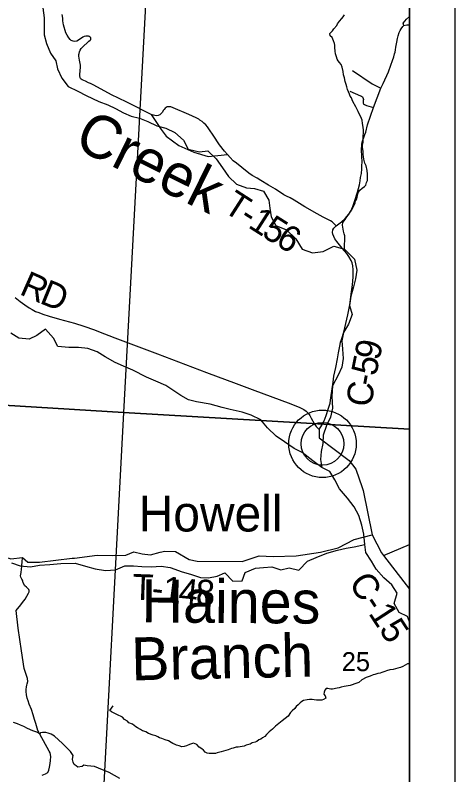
# Model space of a CAD drawing. Extents: x 0 to 45.4, y -2.2 to 22.
# Drawn here: x 8.031 to 9, y 16.232 to 17.906 of the extents above; entities that cross this region are included whole.
import ezdxf

# ---------------------------------------------------------------- set-up
doc = ezdxf.new("R2010")
doc.units = 0
for name, color, linetype in [('GM_X_Corporation', 7, 'Continuous'), ('GM_X_County_Road', 7, 'Continuous'), ('GM_X_County_Road_Text', 7, 'Continuous'), ('GM_X_Minor_River', 7, 'Continuous'), ('GM_X_Minor_River_Text', 7, 'Continuous'), ('GM_X_Section_Text', 7, 'Continuous'), ('GM_X_Township_Road', 7, 'Continuous'), ('GM_X_Township_Road_Text', 7, 'Continuous'), ('GM_X_Unincorporated', 7, 'Continuous'), ('GM_X_Unincorporated_Location', 7, 'Continuous'), ('GM_X_Unincorporated_Text', 7, 'Continuous'), ('SH_Data', 7, 'Continuous')]:
    doc.layers.add(name, color=color, linetype=linetype)

msp = doc.modelspace()

# ---------------------------------------------------------------- linework, layer by layer
at = {"layer": 'GM_X_Corporation'}
for points in [[(5.6021, 14.1), (7.0413, 14.1), (7.1146, 14.1136), (7.5608, 14.2194), (7.6244, 14.2444), (8.0832, 14.3972), (8.4711, 14.5406), (8.5907, 14.5823), (8.8228, 14.6772), (8.9, 14.7192), (8.9, 20.9), (2.1, 20.9)], [(5.6021, 14.1), (7.0413, 14.1), (7.1146, 14.1136), (7.5608, 14.2194), (7.6244, 14.2444), (8.0832, 14.3972), (8.4711, 14.5406), (8.5907, 14.5823), (8.8228, 14.6772), (8.9, 14.7192), (8.9, 20.9), (6.2942, 20.9), (6.2882, 20.8226), (6.2789, 20.7002), (6.2588, 20.2929), (6.2538, 20.2076), (6.2346, 20.0088), (6.2236, 19.8542), (6.181, 19.2539), (6.1763, 19.1885), (6.1061, 18.1607), (5.642, 18.1908)]]:
    msp.add_lwpolyline(points, dxfattribs=at)
for points in [[(7.2262, 18.1039), (8.3245, 18.0384), (8.2701, 17.0306), (7.1661, 17.098)], [(8.9, 16.9941), (8.9, 18.0073), (8.3245, 18.0384), (8.2701, 17.0306)], [(8.2701, 17.0306), (8.2164, 16.0186), (7.1036, 16.0876), (7.1661, 17.098)], [(8.9, 15.9811), (8.9, 16.9941), (8.2701, 17.0306), (8.2164, 16.0186)]]:
    msp.add_lwpolyline(points, close=True, dxfattribs=at)
at = {"layer": 'GM_X_County_Road'}
for points in [[(8.8819, 17.8762), (8.8854, 17.8817), (8.8874, 17.8837), (8.8941, 17.8853), (8.8994, 17.8849), (8.9, 17.8847)], [(8.7009, 16.9934), (8.7068, 17.0031), (8.7118, 17.012), (8.7163, 17.0242), (8.7211, 17.0379), (8.7251, 17.0515), (8.7261, 17.0576), (8.7277, 17.0683), (8.7318, 17.0973), (8.7336, 17.1111), (8.7376, 17.1297), (8.7411, 17.1487), (8.7436, 17.1619), (8.7457, 17.1732), (8.7472, 17.1806), (8.7484, 17.186), (8.7502, 17.1918), (8.7552, 17.2079), (8.7645, 17.2457), (8.7685, 17.2683), (8.7724, 17.2968), (8.7744, 17.3124), (8.7758, 17.3289), (8.776, 17.345), (8.7751, 17.3542), (8.7741, 17.3604), (8.7715, 17.3659), (8.7664, 17.3742), (8.7619, 17.381), (8.752, 17.3929), (8.7402, 17.4073), (8.7359, 17.4134), (8.7334, 17.4184), (8.7313, 17.4235), (8.7302, 17.4272), (8.7313, 17.433), (8.7331, 17.437), (8.7386, 17.4424), (8.7503, 17.451), (8.7586, 17.4583), (8.7666, 17.4681), (8.7713, 17.4751), (8.7732, 17.4799), (8.7752, 17.4848), (8.78, 17.498), (8.7858, 17.5163), (8.7896, 17.5324), (8.7913, 17.5409), (8.7925, 17.5484), (8.794, 17.5575), (8.7949, 17.5677), (8.7951, 17.5731), (8.7955, 17.5843), (8.7952, 17.5936), (8.7947, 17.611), (8.7949, 17.6189), (8.7951, 17.622), (8.7961, 17.6263), (8.7973, 17.631), (8.7996, 17.6369), (8.8018, 17.6433), (8.8039, 17.6488), (8.8076, 17.6649), (8.8208, 17.7029), (8.8371, 17.7454), (8.8419, 17.7558), (8.8535, 17.7816), (8.8592, 17.796), (8.863, 17.8067), (8.8656, 17.8145), (8.8674, 17.8212), (8.8683, 17.8248), (8.8692, 17.83), (8.8703, 17.8357), (8.8722, 17.8471), (8.8736, 17.8547), (8.8754, 17.8611), (8.8777, 17.8682), (8.8794, 17.8723), (8.8819, 17.8762)], [(8.0309, 17.2842), (8.0421, 17.2756), (8.0522, 17.2682), (8.0616, 17.2616), (8.0685, 17.2577), (8.076, 17.2535), (8.083, 17.2507), (8.092, 17.2477), (8.1063, 17.2433), (8.129, 17.2366), (8.1615, 17.2272), (8.1823, 17.2211), (8.2057, 17.2128), (8.2147, 17.2093), (8.2507, 17.1955), (8.3446, 17.16), (8.4525, 17.1191), (8.5181, 17.0946), (8.5595, 17.0791), (8.6325, 17.0518), (8.6568, 17.0426), (8.6675, 17.0376), (8.6726, 17.0333), (8.6765, 17.0295), (8.6802, 17.0243), (8.6831, 17.0183), (8.69, 17.0063), (8.6942, 17), (8.7009, 16.9934), (8.7012, 16.9748), (8.7674, 16.9251), (8.7816, 16.9061), (8.7959, 16.8653), (8.7982, 16.8588), (8.8176, 16.7613)], [(8.8176, 16.7613), (8.8384, 16.7214), (8.8425, 16.7152), (8.9, 16.6414)]]:
    msp.add_lwpolyline(points, dxfattribs=at)
at = {"layer": 'GM_X_Minor_River'}
for points in [[(8.0896, 17.9392), (8.0948, 17.9004), (8.0946, 17.8632), (8.0998, 17.8442), (8.1088, 17.8229), (8.1209, 17.8054), (8.1246, 17.7879), (8.1336, 17.7674), (8.1479, 17.7491), (8.1691, 17.7392), (8.1872, 17.7292), (8.2152, 17.7162), (8.2349, 17.7085), (8.2522, 17.7009), (8.2696, 17.691), (8.287, 17.6841), (8.3052, 17.6794), (8.3233, 17.6718), (8.343, 17.6626), (8.3634, 17.6572), (8.383, 17.648), (8.4019, 17.6312), (8.4124, 17.6107), (8.4374, 17.6053), (8.4556, 17.6075), (8.4737, 17.59), (8.488, 17.5702), (8.5015, 17.5511), (8.5189, 17.5336), (8.5408, 17.5259), (8.5582, 17.5243), (8.5787, 17.5182), (8.5899, 17.4984), (8.5921, 17.4809), (8.5951, 17.4619), (8.6056, 17.4429), (8.629, 17.4329), (8.6494, 17.4131), (8.6637, 17.391), (8.6864, 17.3826), (8.7099, 17.3855), (8.7334, 17.3976), (8.7569, 17.3907), (8.7787, 17.3685), (8.7839, 17.3442), (8.7808, 17.3252), (8.777, 17.3078), (8.7708, 17.2873), (8.7677, 17.2668), (8.7737, 17.247), (8.766, 17.225), (8.7546, 17.2068), (8.7507, 17.1885), (8.7522, 17.1703), (8.7536, 17.1498), (8.7513, 17.1308), (8.7429, 17.1133), (8.7306, 17.0898), (8.729, 17.0662), (8.7305, 17.0404), (8.7258, 17.0206), (8.7174, 17.0017), (8.7098, 16.9804), (8.7089, 16.9622), (8.7058, 16.9447), (8.7042, 16.9272), (8.7072, 16.9097)], [(8.7569, 17.3907), (8.7574, 17.4199), (8.7559, 17.4245), (8.7545, 17.4302), (8.7535, 17.4394), (8.7528, 17.4432), (8.7533, 17.4493), (8.7587, 17.4564), (8.7622, 17.4617), (8.7654, 17.4665), (8.7704, 17.4737), (8.7735, 17.4789), (8.7759, 17.4835), (8.7775, 17.4869), (8.7802, 17.4921), (8.7806, 17.4955), (8.7834, 17.5001), (8.7846, 17.505), (8.7854, 17.5091), (8.7862, 17.5125), (8.7874, 17.5163), (8.7909, 17.5208), (8.7959, 17.5253), (8.8009, 17.5286), (8.804, 17.532), (8.8056, 17.5373), (8.8076, 17.5418), (8.8078, 17.5513), (8.8075, 17.5563), (8.8065, 17.5639), (8.8048, 17.5742), (8.8014, 17.5799), (8.7997, 17.5891), (8.799, 17.594), (8.798, 17.5997), (8.7977, 17.6062), (8.7964, 17.6157), (8.7965, 17.6199), (8.7977, 17.6267), (8.7982, 17.6332), (8.7986, 17.654), (8.7983, 17.659), (8.7972, 17.6636), (8.7969, 17.6677), (8.7955, 17.675), (8.7926, 17.6826), (8.7882, 17.6907), (8.7868, 17.6941), (8.7839, 17.6999), (8.782, 17.7045), (8.7754, 17.7164), (8.774, 17.7198), (8.7722, 17.7244), (8.7696, 17.7279), (8.7678, 17.7321), (8.7656, 17.7374), (8.7638, 17.7424), (8.762, 17.7481), (8.7606, 17.7535), (8.7584, 17.7603), (8.7566, 17.768), (8.7549, 17.7752), (8.7539, 17.7824), (8.7514, 17.792), (8.7496, 17.7973), (8.7459, 17.8019), (8.7429, 17.8058), (8.7407, 17.8096), (8.7389, 17.8142), (8.7367, 17.8211), (8.7361, 17.8268), (8.7359, 17.8352), (8.7356, 17.8401), (8.7349, 17.8443), (8.7327, 17.85), (8.7294, 17.8569), (8.725, 17.8612), (8.7247, 17.8657), (8.7304, 17.8721), (8.7336, 17.8766), (8.7397, 17.8837), (8.7413, 17.8871), (8.746, 17.8931), (8.751, 17.8991), (8.7537, 17.9028), (8.7572, 17.9073)], [(8.9, 16.5695), (8.896, 16.5811), (8.8771, 16.5896), (8.8666, 16.6094), (8.8727, 16.6322), (8.8614, 16.6505), (8.8433, 16.6665), (8.8267, 16.6856), (8.8162, 16.7032), (8.8042, 16.7222), (8.802, 16.7397), (8.7998, 16.7626), (8.7953, 16.7824), (8.7886, 16.8037), (8.7781, 16.8227), (8.7637, 16.8418), (8.7456, 16.8624), (8.7359, 16.8822), (8.7246, 16.9005), (8.7072, 16.9097), (8.6868, 16.9242), (8.6634, 16.9426), (8.646, 16.951), (8.6249, 16.9663), (8.606, 16.9785), (8.5871, 16.9968), (8.5728, 17.0144), (8.5509, 17.0251), (8.5312, 17.0312), (8.5047, 17.0374), (8.4873, 17.042), (8.4609, 17.049), (8.4306, 17.0544), (8.4132, 17.0583), (8.3958, 17.0682), (8.3633, 17.0904), (8.3414, 17.0996), (8.3202, 17.1088), (8.29, 17.1241), (8.2696, 17.1325), (8.2515, 17.1409), (8.2295, 17.1532), (8.2114, 17.1647), (8.191, 17.1716), (8.1706, 17.1739), (8.1493, 17.174), (8.1251, 17.1764), (8.1153, 17.1946), (8.098, 17.2145), (8.079, 17.2001), (8.0616, 17.1926), (8.0389, 17.1942), (8.0215, 17.2056)], [(8.0232, 16.6992), (8.0422, 16.693), (8.0649, 16.6907), (8.0846, 16.6944), (8.1073, 16.6959), (8.1315, 16.6981), (8.1634, 16.6987), (8.186, 16.6918), (8.2072, 16.6864), (8.2299, 16.6825), (8.2519, 16.6839), (8.2731, 16.693), (8.2921, 16.6929), (8.3103, 16.6913), (8.3307, 16.6905), (8.3527, 16.6919), (8.3723, 16.6888), (8.3988, 16.6796), (8.4177, 16.6742), (8.4397, 16.6673), (8.4571, 16.6664), (8.476, 16.6702), (8.4935, 16.677), (8.5108, 16.6586), (8.5313, 16.6593), (8.5382, 16.6783), (8.5609, 16.6874), (8.5783, 16.6888), (8.5965, 16.6903), (8.6162, 16.6841), (8.6351, 16.6886), (8.6563, 16.6832), (8.6753, 16.7029), (8.6943, 16.7112), (8.7178, 16.7203), (8.7413, 16.727), (8.7603, 16.7315), (8.7785, 16.7345), (8.802, 16.7397), (8.8004, 16.739)], [(8.9, 16.4768), (8.8955, 16.4766), (8.8852, 16.4707), (8.8806, 16.4689), (8.8745, 16.4674), (8.8695, 16.466), (8.8638, 16.4646), (8.857, 16.4632), (8.8498, 16.461), (8.8456, 16.4599), (8.8395, 16.4578), (8.8357, 16.4563), (8.83, 16.4553), (8.8239, 16.4535), (8.8201, 16.4524), (8.8132, 16.4498), (8.8048, 16.4466), (8.7949, 16.4418), (8.7883, 16.4354), (8.78, 16.4325), (8.7739, 16.4307), (8.7697, 16.4293), (8.7602, 16.4275), (8.756, 16.4265), (8.7495, 16.425), (8.7453, 16.424), (8.7404, 16.4229), (8.7305, 16.4212), (8.7267, 16.4212), (8.7233, 16.4217), (8.7199, 16.4225), (8.7165, 16.4226), (8.7134, 16.4184), (8.7122, 16.4143), (8.7114, 16.4101), (8.714, 16.4059), (8.7154, 16.4009), (8.7108, 16.3979), (8.7066, 16.3968), (8.7024, 16.3965), (8.6952, 16.3967), (8.69, 16.3975), (8.6858, 16.398), (8.6797, 16.3981), (8.6748, 16.3974), (8.6664, 16.3956), (8.6626, 16.3934), (8.6592, 16.3904), (8.6549, 16.3863), (8.6507, 16.383), (8.6476, 16.3781), (8.6414, 16.3732), (8.638, 16.3691), (8.6329, 16.3616), (8.6198, 16.3511), (8.6118, 16.3452), (8.6049, 16.3392), (8.5983, 16.3328), (8.591, 16.3265), (8.5849, 16.3209), (8.5814, 16.3168), (8.576, 16.3138), (8.5722, 16.3105), (8.5684, 16.309), (8.5638, 16.3056), (8.5599, 16.3042), (8.5535, 16.3024), (8.5493, 16.2998), (8.5405, 16.2977), (8.5356, 16.2955), (8.5268, 16.2937), (8.5226, 16.293), (8.5181, 16.2927), (8.5116, 16.2909), (8.5078, 16.2899), (8.5044, 16.2888), (8.5006, 16.2869), (8.4853, 16.2826), (8.4819, 16.2819), (8.4766, 16.2805), (8.4724, 16.279), (8.4652, 16.2788), (8.4588, 16.2793), (8.4542, 16.2801), (8.4501, 16.2821), (8.446, 16.2867), (8.4426, 16.2891), (8.4363, 16.2934), (8.4311, 16.2992), (8.4243, 16.3016), (8.4194, 16.3005), (8.4152, 16.299), (8.4087, 16.2961), (8.4033, 16.2943), (8.3984, 16.294), (8.3928, 16.296), (8.3867, 16.2976)], [(8.3867, 16.2976), (8.3834, 16.2992), (8.3788, 16.3008), (8.3751, 16.3032), (8.3691, 16.3067), (8.3616, 16.3091), (8.3544, 16.3119), (8.3495, 16.3135), (8.3458, 16.3158), (8.3409, 16.3178), (8.3352, 16.3198), (8.3247, 16.323), (8.3187, 16.327), (8.3149, 16.3282), (8.3115, 16.3294), (8.3074, 16.3317), (8.3003, 16.336), (8.2969, 16.338), (8.2894, 16.3438), (8.2819, 16.347), (8.2786, 16.3505), (8.2718, 16.3544), (8.2673, 16.359), (8.255, 16.3653), (8.2474, 16.3689), (8.2437, 16.3712), (8.2396, 16.3736), (8.2473, 16.3841)]]:
    msp.add_lwpolyline(points, dxfattribs=at)
at = {"layer": 'GM_X_Township_Road'}
msp.add_line((8.8425, 16.7152), (8.9, 16.7397), dxfattribs=at)
for points in [[(8.4296, 17.6803), (8.414, 17.6873), (8.3792, 17.7021), (8.3739, 17.7042), (8.3719, 17.7047), (8.3693, 17.7047), (8.3663, 17.7043), (8.3638, 17.7031), (8.3616, 17.7011), (8.3594, 17.6987), (8.3577, 17.6968), (8.3547, 17.6922), (8.3524, 17.6888), (8.3496, 17.6864), (8.346, 17.6851), (8.3423, 17.6846), (8.3388, 17.685), (8.3356, 17.6859), (8.3309, 17.6877), (8.3143, 17.6954), (8.2991, 17.7038), (8.2773, 17.7147), (8.259, 17.7234), (8.2436, 17.7305), (8.2042, 17.7518), (8.1971, 17.7556), (8.1928, 17.7575), (8.1858, 17.7606), (8.1787, 17.7638), (8.1764, 17.7653), (8.1751, 17.7668), (8.1745, 17.768), (8.174, 17.7695), (8.1737, 17.7714), (8.1737, 17.7733), (8.1739, 17.7758), (8.1746, 17.7836), (8.175, 17.7916), (8.1747, 17.7963), (8.1731, 17.8071), (8.1717, 17.8158), (8.1715, 17.8198), (8.1718, 17.8221), (8.1728, 17.8258), (8.174, 17.829), (8.1765, 17.8328), (8.1785, 17.8352), (8.1935, 17.849), (8.1961, 17.8513), (8.1975, 17.8528), (8.1981, 17.8545), (8.1976, 17.8562), (8.1963, 17.8582), (8.1941, 17.8592), (8.1924, 17.86), (8.1897, 17.8602), (8.1869, 17.8604), (8.1834, 17.8593), (8.18, 17.8576), (8.173, 17.8528), (8.1666, 17.8494), (8.1629, 17.8481), (8.1587, 17.8488), (8.1543, 17.8506), (8.1519, 17.8531), (8.149, 17.8565), (8.1455, 17.8623), (8.143, 17.8673), (8.1409, 17.8724), (8.1389, 17.8796), (8.1379, 17.885), (8.1364, 17.8939), (8.1358, 17.8999), (8.1348, 17.9078)], [(8.8874, 17.8837), (8.8861, 17.8886), (8.8938, 17.8973), (8.9, 17.9033)], [(8.7745, 17.7842), (8.8181, 17.755), (8.8371, 17.7454)], [(8.7686, 17.7389), (8.7919, 17.7289), (8.7943, 17.7275), (8.7962, 17.7264), (8.7973, 17.7249), (8.7983, 17.7227), (8.7985, 17.7207), (8.7983, 17.7184), (8.7977, 17.7165), (8.7978, 17.7147), (8.7982, 17.7122), (8.7991, 17.7106), (8.8007, 17.7092), (8.8051, 17.7076), (8.8208, 17.7029)], [(8.3309, 17.6877), (8.3529, 17.6542), (8.364, 17.6394), (8.3918, 17.619), (8.4251, 17.6042), (8.4565, 17.595), (8.4991, 17.5995)], [(8.7386, 17.4424), (8.7328, 17.4479), (8.7298, 17.4508), (8.7261, 17.4533), (8.7098, 17.4615), (8.6966, 17.4687), (8.6698, 17.4843), (8.6458, 17.4987), (8.6372, 17.504), (8.6293, 17.5075), (8.623, 17.5107), (8.6045, 17.5226), (8.5895, 17.5317), (8.5726, 17.5417), (8.5645, 17.5468), (8.5536, 17.5528), (8.5461, 17.558), (8.5304, 17.5705), (8.5185, 17.5799), (8.5114, 17.5856), (8.5049, 17.5929), (8.4991, 17.5995), (8.4927, 17.6065), (8.4817, 17.6209), (8.4672, 17.6417), (8.4592, 17.654), (8.4547, 17.6604), (8.4514, 17.6644), (8.4472, 17.6685), (8.4429, 17.6721), (8.4384, 17.6751), (8.4355, 17.6772), (8.4315, 17.6794), (8.4296, 17.6803)], [(7.8331, 16.8132), (7.8415, 16.8132), (7.8558, 16.8108), (7.8605, 16.806), (7.8754, 16.8018), (7.8935, 16.7679), (7.9042, 16.7489), (7.9136, 16.7398), (7.9276, 16.7367), (7.9492, 16.7322), (7.9697, 16.728), (8, 16.7147), (8.0212, 16.7078), (8.0471, 16.7112), (8.0591, 16.7006), (8.0848, 16.7005), (8.1565, 16.7093), (8.1615, 16.7099)], [(8.1615, 16.7099), (8.2117, 16.7161), (8.2462, 16.7153), (8.2746, 16.7164), (8.2928, 16.7233), (8.3106, 16.7191), (8.3295, 16.7172), (8.3504, 16.7225), (8.361, 16.7252), (8.3844, 16.7244), (8.4147, 16.7069), (8.4322, 16.7031), (8.5314, 16.7026), (8.5685, 16.7148), (8.6, 16.7136), (8.6507, 16.7151), (8.7041, 16.7231), (8.7431, 16.7326), (8.7784, 16.7504), (8.8176, 16.7613)], [(8.0765, 16.3455), (8.0739, 16.3537), (8.0704, 16.3646), (8.0667, 16.3758), (8.062, 16.388), (8.0594, 16.3953), (8.0576, 16.4014), (8.0563, 16.4081), (8.0553, 16.4157), (8.0555, 16.4205), (8.0559, 16.4263), (8.0564, 16.4294), (8.0573, 16.433), (8.0592, 16.4375), (8.0581, 16.4447), (8.0508, 16.4664), (8.0451, 16.5056), (8.0379, 16.555), (8.0335, 16.5944), (8.0437, 16.6071), (8.0474, 16.6121), (8.0531, 16.6191), (8.0603, 16.6325), (8.0618, 16.6356), (8.062, 16.6383), (8.061, 16.6406), (8.056, 16.6454), (8.052, 16.649), (8.0484, 16.6552), (8.0478, 16.6588), (8.0471, 16.6609), (8.0457, 16.6633), (8.0436, 16.6676), (8.043, 16.6709), (8.0432, 16.6741), (8.0442, 16.6782), (8.0452, 16.6855), (8.0454, 16.6909), (8.0458, 16.6944), (8.0463, 16.7005), (8.0471, 16.7112)], [(8.2619, 16.2243), (8.2383, 16.2374), (8.2149, 16.247), (8.2059, 16.2506), (8.1898, 16.2521), (8.1827, 16.2532), (8.1784, 16.2506), (8.169, 16.2491), (8.1656, 16.2521), (8.1612, 16.2551), (8.1589, 16.2603), (8.1577, 16.2662), (8.158, 16.2711), (8.1585, 16.2746), (8.1574, 16.2769), (8.1533, 16.2835), (8.1353, 16.3011), (8.1174, 16.3173), (8.1104, 16.3216), (8.1041, 16.3241), (8.0984, 16.3254), (8.0916, 16.3252), (8.0872, 16.3244), (8.0854, 16.3214), (8.0836, 16.3233), (8.0786, 16.326), (8.0699, 16.3291), (8.0581, 16.3345), (8.0498, 16.3384), (8.043, 16.3417), (8.0365, 16.3444), (8.0271, 16.3477)], [(8.0906, 16.231), (8.0979, 16.2343), (8.1027, 16.2375), (8.1052, 16.2421), (8.107, 16.2488), (8.1082, 16.2569), (8.1087, 16.264), (8.1093, 16.2724), (8.1083, 16.2802), (8.1061, 16.2845), (8.0856, 16.3214), (8.0812, 16.33), (8.0765, 16.3455)]]:
    msp.add_lwpolyline(points, dxfattribs=at)
at = {"layer": 'GM_X_Unincorporated'}
for radius in [0.0744, 0.0472]:
    msp.add_circle((8.7084, 16.9617), radius, dxfattribs=at)
at = {"layer": 'GM_X_Unincorporated_Location'}
msp.add_line((8.7084, 16.9617), (8.7084, 16.9617), dxfattribs=at)
at = {"layer": 'SH_Data'}
for p, q in [((9, 21), (9, 14)), ((8.9, 20.9), (8.9, 14.1))]:
    msp.add_line(p, q, dxfattribs=at)

# ---------------------------------------------------------------- texts
at = {"layer": 'GM_X_County_Road_Text'}
for s, height, rotation, p in [('R', 0.0568, 336.144, (8.0382, 17.2922)), ('D', 0.0568, 337.8426, (8.0826, 17.2726)), ('9', 0.0568, 78.1389, (8.8335, 17.1435)), ('5', 0.0568, 78.5958, (8.8266, 17.1093)), ('-', 0.0568, 79.7983, (8.8225, 17.0867)), ('C', 0.0568, 82.2918, (8.8164, 17.0411)), ('C-15', 0.05682, 303.0238, (8.7647, 16.6555))]:
    msp.add_text(s, height=height, rotation=rotation, dxfattribs=at).set_placement(p)
at = {"layer": 'GM_X_Minor_River_Text'}
for s, height, rotation, p in [('Creek', 0.0947, 333.7756, (8.1569, 17.6162)), ('Haines', 0.09469, 359.5508, (8.3093, 16.5683)), ('Branch', 0.09469, 1.2147, (8.2876, 16.4401))]:
    msp.add_text(s, height=height, rotation=rotation, dxfattribs=at).set_placement(p)
at = {"layer": 'GM_X_Section_Text'}
msp.add_text('25', height=0.04186, rotation=0, dxfattribs=at).set_placement((8.7508, 16.4606))
at = {"layer": 'GM_X_Township_Road_Text'}
for s, rotation, p in [('T', 327.265, (8.4867, 17.4755)), ('-', 327.2813, (8.5224, 17.4525)), ('1', 327.3352, (8.5421, 17.4399)), ('5', 327.5691, (8.5718, 17.4208)), ('6', 328.6213, (8.6023, 17.4015)), ('T', 357.9714, (8.2886, 16.6182)), ('1', 352.6917, (8.3529, 16.6143)), ('4', 354.1461, (8.3892, 16.6096)), ('8', 358.4968, (8.4287, 16.6058)), ('-', 353.7958, (8.33, 16.6167))]:
    msp.add_text(s, height=0.0568, rotation=rotation, dxfattribs=at).set_placement(p)
at = {"layer": 'GM_X_Unincorporated_Text'}
msp.add_text('Howell', height=0.07898, rotation=0, dxfattribs=at).set_placement((8.3033, 16.7684))

doc.saveas('drawing.dxf')
